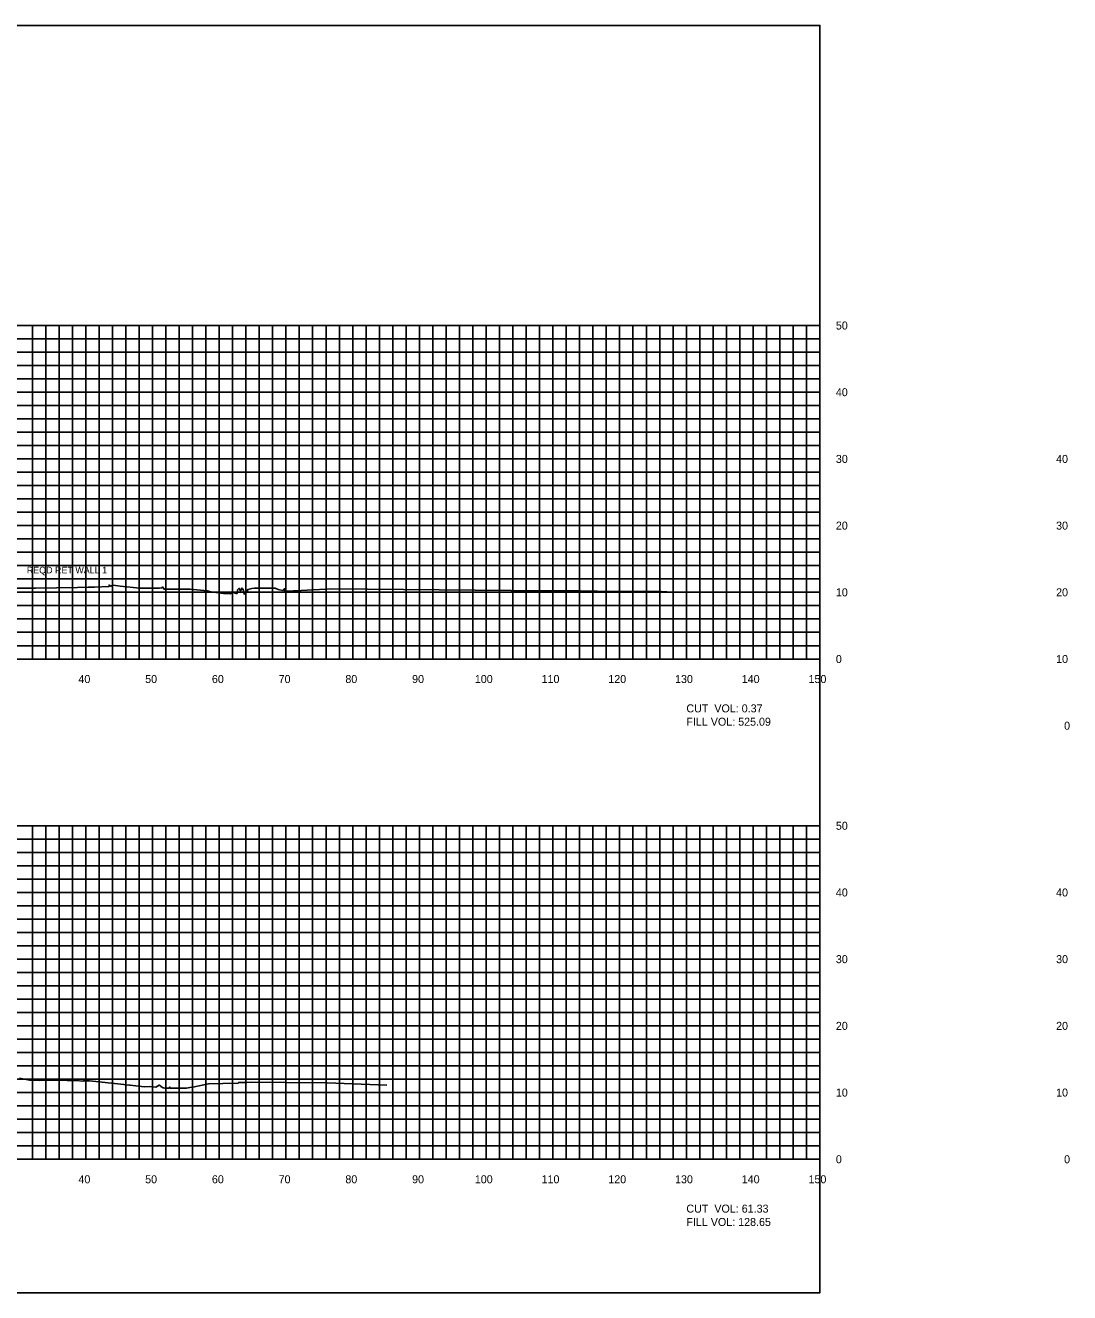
# Model space of a CAD drawing. Extents: x 1797652 to 1804145, y 245981 to 250269.
# Drawn here: x 1802661.9 to 1802818.4, y 250079.4 to 250269.4 of the extents above; entities that cross this region are included whole.
import ezdxf

# ---------------------------------------------------------------- set-up
doc = ezdxf.new("R2010")
doc.units = 0
for name, color, linetype in [('10', 7, 'Continuous'), ('3', 7, 'Continuous'), ('31', 7, 'Continuous'), ('60', 7, 'Continuous'), ('ANNO-TXT', 7, 'Continuous'), ('Level 62', 7, 'Continuous'), ('M-ROADS', 7, 'Continuous')]:
    doc.layers.add(name, color=color, linetype=linetype)

msp = doc.modelspace()

# ---------------------------------------------------------------- linework, layer by layer
msp.add_lwpolyline([(1802481, 250079.43), (1802781, 250079.43), (1802781, 250269.43), (1802481, 250269.43)], close=True)
at = {"layer": '60'}
for p, q in [((1802781, 250174.43), (1802781, 250224.43)), ((1802781.06, 250224.43), (1802781, 250224.43)), ((1802781.06, 250214.43), (1802781, 250214.43)), ((1802781.06, 250204.43), (1802781, 250204.43)), ((1802781.06, 250194.43), (1802781, 250194.43)), ((1802781.06, 250184.43), (1802781, 250184.43)), ((1802481, 250174.43), (1802781, 250174.43)), ((1802671, 250174.37), (1802671, 250174.43)), ((1802681, 250174.37), (1802681, 250174.43)), ((1802691, 250174.37), (1802691, 250174.43)), ((1802701, 250174.37), (1802701, 250174.43)), ((1802711, 250174.37), (1802711, 250174.43)), ((1802721, 250174.37), (1802721, 250174.43)), ((1802731, 250174.37), (1802731, 250174.43)), ((1802741, 250174.37), (1802741, 250174.43)), ((1802751, 250174.37), (1802751, 250174.43)), ((1802761, 250174.37), (1802761, 250174.43)), ((1802771, 250174.37), (1802771, 250174.43)), ((1802781, 250174.37), (1802781, 250174.43)), ((1802781.06, 250174.43), (1802781, 250174.43)), ((1802781, 250099.43), (1802781, 250149.43)), ((1802781.06, 250149.43), (1802781, 250149.43)), ((1802781.06, 250139.43), (1802781, 250139.43)), ((1802781.06, 250129.43), (1802781, 250129.43)), ((1802781.06, 250119.43), (1802781, 250119.43)), ((1802781.06, 250109.43), (1802781, 250109.43)), ((1802481, 250099.43), (1802781, 250099.43)), ((1802671, 250099.37), (1802671, 250099.43)), ((1802681, 250099.37), (1802681, 250099.43)), ((1802691, 250099.37), (1802691, 250099.43)), ((1802701, 250099.37), (1802701, 250099.43)), ((1802711, 250099.37), (1802711, 250099.43)), ((1802721, 250099.37), (1802721, 250099.43)), ((1802731, 250099.37), (1802731, 250099.43)), ((1802741, 250099.37), (1802741, 250099.43)), ((1802751, 250099.37), (1802751, 250099.43)), ((1802761, 250099.37), (1802761, 250099.43)), ((1802771, 250099.37), (1802771, 250099.43)), ((1802781, 250099.37), (1802781, 250099.43)), ((1802781.06, 250099.43), (1802781, 250099.43))]:
    msp.add_line(p, q, dxfattribs=at)
at = {"layer": 'Level 62'}
for p, q in [((1802481, 250224.43), (1802781, 250224.43)), ((1802663, 250174.43), (1802663, 250224.43)), ((1802665, 250174.43), (1802665, 250224.43)), ((1802667, 250174.43), (1802667, 250224.43)), ((1802669, 250174.43), (1802669, 250224.43)), ((1802671, 250174.43), (1802671, 250224.43)), ((1802673, 250174.43), (1802673, 250224.43)), ((1802675, 250174.43), (1802675, 250224.43)), ((1802677, 250174.43), (1802677, 250224.43)), ((1802679, 250174.43), (1802679, 250224.43)), ((1802681, 250174.43), (1802681, 250224.43)), ((1802683, 250174.43), (1802683, 250224.43)), ((1802685, 250174.43), (1802685, 250224.43)), ((1802687, 250174.43), (1802687, 250224.43)), ((1802689, 250174.43), (1802689, 250224.43)), ((1802691, 250174.43), (1802691, 250224.43)), ((1802693, 250174.43), (1802693, 250224.43)), ((1802695, 250174.43), (1802695, 250224.43)), ((1802697, 250174.43), (1802697, 250224.43)), ((1802699, 250174.43), (1802699, 250224.43)), ((1802701, 250174.43), (1802701, 250224.43)), ((1802703, 250174.43), (1802703, 250224.43)), ((1802705, 250174.43), (1802705, 250224.43)), ((1802707, 250174.43), (1802707, 250224.43)), ((1802709, 250174.43), (1802709, 250224.43)), ((1802711, 250174.43), (1802711, 250224.43)), ((1802713, 250174.43), (1802713, 250224.43)), ((1802715, 250174.43), (1802715, 250224.43)), ((1802717, 250174.43), (1802717, 250224.43)), ((1802719, 250174.43), (1802719, 250224.43)), ((1802721, 250174.43), (1802721, 250224.43)), ((1802723, 250174.43), (1802723, 250224.43)), ((1802725, 250174.43), (1802725, 250224.43)), ((1802727, 250174.43), (1802727, 250224.43)), ((1802729, 250174.43), (1802729, 250224.43)), ((1802731, 250174.43), (1802731, 250224.43)), ((1802733, 250174.43), (1802733, 250224.43)), ((1802735, 250174.43), (1802735, 250224.43)), ((1802737, 250174.43), (1802737, 250224.43)), ((1802739, 250174.43), (1802739, 250224.43)), ((1802741, 250174.43), (1802741, 250224.43)), ((1802743, 250174.43), (1802743, 250224.43)), ((1802745, 250174.43), (1802745, 250224.43)), ((1802747, 250174.43), (1802747, 250224.43)), ((1802749, 250174.43), (1802749, 250224.43)), ((1802751, 250174.43), (1802751, 250224.43)), ((1802753, 250174.43), (1802753, 250224.43)), ((1802755, 250174.43), (1802755, 250224.43)), ((1802757, 250174.43), (1802757, 250224.43)), ((1802759, 250174.43), (1802759, 250224.43)), ((1802761, 250174.43), (1802761, 250224.43)), ((1802763, 250174.43), (1802763, 250224.43)), ((1802765, 250174.43), (1802765, 250224.43)), ((1802767, 250174.43), (1802767, 250224.43)), ((1802769, 250174.43), (1802769, 250224.43)), ((1802771, 250174.43), (1802771, 250224.43)), ((1802773, 250174.43), (1802773, 250224.43)), ((1802775, 250174.43), (1802775, 250224.43)), ((1802777, 250174.43), (1802777, 250224.43)), ((1802779, 250174.43), (1802779, 250224.43)), ((1802781, 250174.43), (1802781, 250224.43)), ((1802481, 250222.43), (1802781, 250222.43)), ((1802481, 250220.43), (1802781, 250220.43)), ((1802481, 250218.43), (1802781, 250218.43)), ((1802481, 250216.43), (1802781, 250216.43)), ((1802481, 250214.43), (1802781, 250214.43)), ((1802481, 250212.43), (1802781, 250212.43)), ((1802481, 250210.43), (1802781, 250210.43)), ((1802481, 250208.43), (1802781, 250208.43)), ((1802481, 250206.43), (1802781, 250206.43)), ((1802481, 250204.43), (1802781, 250204.43)), ((1802481, 250202.43), (1802781, 250202.43)), ((1802481, 250200.43), (1802781, 250200.43)), ((1802481, 250198.43), (1802781, 250198.43)), ((1802481, 250196.43), (1802781, 250196.43)), ((1802481, 250194.43), (1802781, 250194.43)), ((1802481, 250192.43), (1802781, 250192.43)), ((1802481, 250190.43), (1802781, 250190.43)), ((1802481, 250188.43), (1802781, 250188.43)), ((1802481, 250186.43), (1802781, 250186.43)), ((1802481, 250184.43), (1802781, 250184.43)), ((1802481, 250182.43), (1802781, 250182.43)), ((1802481, 250180.43), (1802781, 250180.43)), ((1802481, 250178.43), (1802781, 250178.43)), ((1802481, 250176.43), (1802781, 250176.43)), ((1802481, 250174.43), (1802781, 250174.43)), ((1802481, 250149.43), (1802781, 250149.43)), ((1802663, 250099.43), (1802663, 250149.43)), ((1802665, 250099.43), (1802665, 250149.43)), ((1802667, 250099.43), (1802667, 250149.43)), ((1802669, 250099.43), (1802669, 250149.43)), ((1802671, 250099.43), (1802671, 250149.43)), ((1802673, 250099.43), (1802673, 250149.43)), ((1802675, 250099.43), (1802675, 250149.43)), ((1802677, 250099.43), (1802677, 250149.43)), ((1802679, 250099.43), (1802679, 250149.43)), ((1802681, 250099.43), (1802681, 250149.43)), ((1802683, 250099.43), (1802683, 250149.43)), ((1802685, 250099.43), (1802685, 250149.43)), ((1802687, 250099.43), (1802687, 250149.43)), ((1802689, 250099.43), (1802689, 250149.43)), ((1802691, 250099.43), (1802691, 250149.43)), ((1802693, 250099.43), (1802693, 250149.43)), ((1802695, 250099.43), (1802695, 250149.43)), ((1802697, 250099.43), (1802697, 250149.43)), ((1802699, 250099.43), (1802699, 250149.43)), ((1802701, 250099.43), (1802701, 250149.43)), ((1802703, 250099.43), (1802703, 250149.43)), ((1802705, 250099.43), (1802705, 250149.43)), ((1802707, 250099.43), (1802707, 250149.43)), ((1802709, 250099.43), (1802709, 250149.43)), ((1802711, 250099.43), (1802711, 250149.43)), ((1802713, 250099.43), (1802713, 250149.43)), ((1802715, 250099.43), (1802715, 250149.43)), ((1802717, 250099.43), (1802717, 250149.43)), ((1802719, 250099.43), (1802719, 250149.43)), ((1802721, 250099.43), (1802721, 250149.43)), ((1802723, 250099.43), (1802723, 250149.43)), ((1802725, 250099.43), (1802725, 250149.43)), ((1802727, 250099.43), (1802727, 250149.43)), ((1802729, 250099.43), (1802729, 250149.43)), ((1802731, 250099.43), (1802731, 250149.43)), ((1802733, 250099.43), (1802733, 250149.43)), ((1802735, 250099.43), (1802735, 250149.43)), ((1802737, 250099.43), (1802737, 250149.43)), ((1802739, 250099.43), (1802739, 250149.43)), ((1802741, 250099.43), (1802741, 250149.43)), ((1802743, 250099.43), (1802743, 250149.43)), ((1802745, 250099.43), (1802745, 250149.43)), ((1802747, 250099.43), (1802747, 250149.43)), ((1802749, 250099.43), (1802749, 250149.43)), ((1802751, 250099.43), (1802751, 250149.43)), ((1802753, 250099.43), (1802753, 250149.43)), ((1802755, 250099.43), (1802755, 250149.43)), ((1802757, 250099.43), (1802757, 250149.43)), ((1802759, 250099.43), (1802759, 250149.43)), ((1802761, 250099.43), (1802761, 250149.43)), ((1802763, 250099.43), (1802763, 250149.43)), ((1802765, 250099.43), (1802765, 250149.43)), ((1802767, 250099.43), (1802767, 250149.43)), ((1802769, 250099.43), (1802769, 250149.43)), ((1802771, 250099.43), (1802771, 250149.43)), ((1802773, 250099.43), (1802773, 250149.43)), ((1802775, 250099.43), (1802775, 250149.43)), ((1802777, 250099.43), (1802777, 250149.43)), ((1802779, 250099.43), (1802779, 250149.43)), ((1802781, 250099.43), (1802781, 250149.43)), ((1802481, 250147.43), (1802781, 250147.43)), ((1802481, 250145.43), (1802781, 250145.43)), ((1802481, 250143.43), (1802781, 250143.43)), ((1802481, 250141.43), (1802781, 250141.43)), ((1802481, 250139.43), (1802781, 250139.43)), ((1802481, 250137.43), (1802781, 250137.43)), ((1802481, 250135.43), (1802781, 250135.43)), ((1802481, 250133.43), (1802781, 250133.43)), ((1802481, 250131.43), (1802781, 250131.43)), ((1802481, 250129.43), (1802781, 250129.43)), ((1802481, 250127.43), (1802781, 250127.43)), ((1802481, 250125.43), (1802781, 250125.43)), ((1802481, 250123.43), (1802781, 250123.43)), ((1802481, 250121.43), (1802781, 250121.43)), ((1802481, 250119.43), (1802781, 250119.43)), ((1802481, 250117.43), (1802781, 250117.43)), ((1802481, 250115.43), (1802781, 250115.43)), ((1802481, 250113.43), (1802781, 250113.43)), ((1802481, 250111.43), (1802781, 250111.43)), ((1802481, 250109.43), (1802781, 250109.43)), ((1802481, 250107.43), (1802781, 250107.43)), ((1802481, 250105.43), (1802781, 250105.43)), ((1802481, 250103.43), (1802781, 250103.43)), ((1802481, 250101.43), (1802781, 250101.43)), ((1802481, 250099.43), (1802781, 250099.43))]:
    msp.add_line(p, q, dxfattribs=at)
at = {"layer": 'M-ROADS'}
for points in [[(1802660.61, 250185.03), (1802663.49, 250185.05), (1802669.75, 250185.16), (1802671.38, 250185.2), (1802672.31, 250185.18), (1802674.46, 250185.28), (1802674.5, 250185.51), (1802674.76, 250185.34), (1802675.12, 250185.49), (1802676.15, 250185.37), (1802679.11, 250185.07), (1802680.66, 250185.07), (1802682.04, 250185.07), (1802682.44, 250185.09), (1802682.49, 250185.25), (1802682.73, 250184.92), (1802682.73, 250184.91), (1802682.84, 250184.92), (1802684.08, 250184.9), (1802685.39, 250184.9), (1802686.63, 250184.9), (1802689.17, 250184.65), (1802689.74, 250184.52), (1802691.65, 250184.23), (1802692.65, 250184.22), (1802693.14, 250184.41), (1802693.53, 250184.27), (1802693.63, 250184.25), (1802693.68, 250184.24), (1802693.76, 250184.78), (1802693.98, 250185.04), (1802694.18, 250184.59), (1802694.41, 250185.07), (1802694.49, 250184.83), (1802694.57, 250184.91), (1802694.75, 250184.15), (1802694.82, 250184.23), (1802694.9, 250184.16), (1802695.19, 250184.53), (1802695.29, 250184.87), (1802695.89, 250185.02), (1802696.26, 250185.07), (1802696.33, 250185.07), (1802696.44, 250185.04), (1802698.68, 250185.04), (1802698.89, 250185.04), (1802699.37, 250185.07), (1802699.81, 250184.84), (1802700.02, 250184.81), (1802700.56, 250184.7), (1802700.77, 250184.96), (1802700.82, 250184.96), (1802700.85, 250184.61), (1802700.85, 250184.61), (1802700.85, 250184.61), (1802700.86, 250184.61), (1802703.3, 250184.69), (1802707.84, 250184.96), (1802734.76, 250184.69), (1802745.14, 250184.66), (1802750.15, 250184.56), (1802753.6, 250184.55), (1802754.55, 250184.56), (1802756.62, 250184.53), (1802757.2, 250184.53), (1802758.05, 250184.5)], [(1802661.09, 250111.57), (1802662.58, 250111.28), (1802664.04, 250111.26), (1802665.56, 250111.27), (1802666.41, 250111.27), (1802668.19, 250111.25), (1802669.02, 250111.26), (1802669.52, 250111.25), (1802670.56, 250111.16), (1802670.71, 250111.2), (1802671.56, 250111.17), (1802676.27, 250110.67), (1802677.57, 250110.52), (1802677.66, 250110.52), (1802679.76, 250110.27), (1802680.5, 250110.34), (1802681.52, 250110.26), (1802682, 250110.56), (1802682.19, 250110.45), (1802682.24, 250110.36), (1802682.6, 250110.13), (1802682.87, 250110.1), (1802683.47, 250110.1), (1802683.47, 250110.1), (1802683.48, 250110.1), (1802683.59, 250110.26), (1802683.63, 250110.11), (1802683.79, 250110.07), (1802684.36, 250110.07), (1802686.06, 250110.07), (1802686.91, 250110.23), (1802687.05, 250110.24), (1802689.39, 250110.72), (1802691.53, 250110.77), (1802693.85, 250110.84), (1802693.92, 250110.95), (1802695.13, 250110.93), (1802695.78, 250111.01), (1802701.09, 250110.94), (1802707.16, 250110.89), (1802716.1, 250110.55)]]:
    msp.add_lwpolyline(points, dxfattribs=at)

# ---------------------------------------------------------------- texts
at = {"layer": '10'}
for s, p in [('40', (1802669.9, 250170.83)), ('50', (1802679.9, 250170.83)), ('60', (1802689.9, 250170.83)), ('70', (1802699.9, 250170.83)), ('80', (1802709.9, 250170.83)), ('90', (1802719.9, 250170.83)), ('100', (1802729.3, 250170.83)), ('110', (1802739.3, 250170.83)), ('120', (1802749.3, 250170.83)), ('130', (1802759.3, 250170.83)), ('140', (1802769.3, 250170.83)), ('150', (1802779.3, 250170.83)), ('40', (1802669.9, 250095.83)), ('50', (1802679.9, 250095.83)), ('60', (1802689.9, 250095.83)), ('70', (1802699.9, 250095.83)), ('80', (1802709.9, 250095.83)), ('90', (1802719.9, 250095.83)), ('100', (1802729.3, 250095.83)), ('110', (1802739.3, 250095.83)), ('120', (1802749.3, 250095.83)), ('130', (1802759.3, 250095.83)), ('140', (1802769.3, 250095.83)), ('150', (1802779.3, 250095.83))]:
    msp.add_text(s, height=1.2, dxfattribs=at).set_placement(p)
at = {"layer": '3'}
msp.add_text('REQD RET WALL 1', height=1, dxfattribs=at).set_placement((1802662.16, 250187.26))
at = {"layer": '31'}
for s, p in [('50', (1802783.4, 250223.83)), ('40', (1802783.4, 250213.83)), ('30', (1802783.4, 250203.83)), ('40', (1802816.4, 250203.83)), ('20', (1802783.4, 250193.83)), ('30', (1802816.4, 250193.83)), ('10', (1802783.4, 250183.83)), ('20', (1802816.4, 250183.83)), ('0', (1802783.4, 250173.83)), ('10', (1802816.4, 250173.83)), ('0', (1802817.6, 250163.83)), ('50', (1802783.4, 250148.83)), ('40', (1802783.4, 250138.83)), ('40', (1802816.4, 250138.83)), ('30', (1802783.4, 250128.83)), ('30', (1802816.4, 250128.83)), ('20', (1802783.4, 250118.83)), ('20', (1802816.4, 250118.83)), ('10', (1802783.4, 250108.83)), ('10', (1802816.4, 250108.83)), ('0', (1802783.4, 250098.83)), ('0', (1802817.6, 250098.83))]:
    msp.add_text(s, height=1.2, dxfattribs=at).set_placement(p)
at = {"layer": 'ANNO-TXT'}
for s, p in [('CUT  VOL: 0.37', (1802761, 250166.43)), ('FILL VOL: 525.09', (1802761, 250164.43)), ('CUT  VOL: 61.33', (1802761, 250091.43)), ('FILL VOL: 128.65', (1802761, 250089.43))]:
    msp.add_text(s, height=1.2, dxfattribs=at).set_placement(p)

doc.saveas('drawing.dxf')
